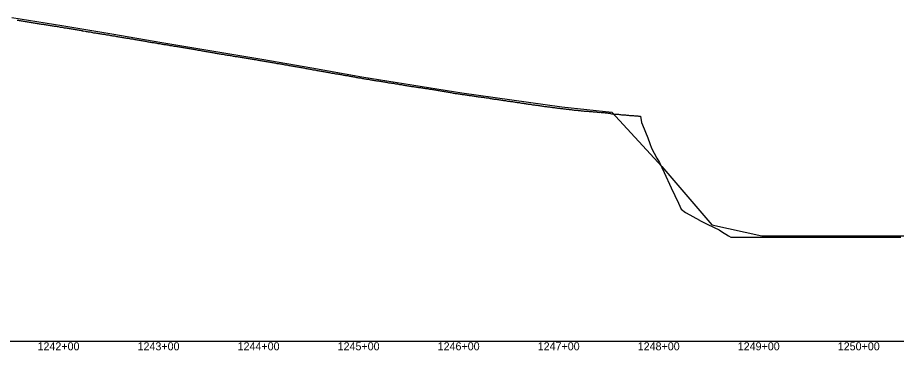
# Model space of a CAD drawing. Extents: x -3793 to 50787, y -1075 to 6138.
# Drawn here: x 11533 to 12412, y -1009 to -677 of the extents above; entities that cross this region are included whole.
import ezdxf

# ---------------------------------------------------------------- set-up
doc = ezdxf.new("R2010")
doc.units = 0
for name, color, linetype in [('RD_DDB_Profile_EX', 7, 'Continuous'), ('RD_DDB_Profile_PR', 7, 'Continuous'), ('RD_DDB_StaTX', 7, 'Continuous'), ('RD_GPK_Profile_Cell', 7, 'Continuous')]:
    doc.layers.add(name, color=color, linetype=linetype)

msp = doc.modelspace()

# ---------------------------------------------------------------- linework, layer by layer
at = {"layer": 'RD_DDB_Profile_EX'}
for points in [[(11532.766979, -678.98741), (11533.770655, -679.093735), (11534.765852, -679.29383), (11535.769737, -679.537725), (11536.765284, -679.63993), (11537.760475, -679.84009), (11538.769144, -679.940305), (11539.764149, -680.188555), (11540.759673, -680.338745), (11541.763232, -680.44254), (11542.758748, -680.7445), (11543.75394, -680.7982), (11544.757823, -680.94642), (11545.752841, -681.04824), (11546.756725, -681.298255), (11547.752219, -681.45), (11548.752221, -681.69835), (11549.756105, -681.8), (11550.751298, -682), (11551.746608, -682.153155), (11552.750219, -682.307825), (11553.745681, -682.501535), (11554.749299, -682.60913), (11555.744755, -682.70894), (11556.7398, -682.952915), (11557.743684, -683.057235), (11558.739124, -683.20708), (11559.739154, -683.358105), (11560.743036, -683.558035), (11561.641476, -683.661995), (11562.636702, -683.813015), (11563.640337, -684.01161), (11564.639413, -684.110495), (11565.634539, -684.358955), (11566.638401, -684.460145), (11567.633743, -684.611125), (11568.637268, -684.86348), (11569.627817, -684.963485), (11570.631464, -685.21093), (11571.635325, -685.264445)], [(11571.635325, -685.264445), (11572.630452, -685.51054), (11573.634313, -685.517405), (11574.629329, -685.86467), (11575.628388, -686.0638), (11576.623515, -686.161175), (11577.627376, -686.217705), (11578.631237, -686.51315), (11579.626364, -686.612755), (11580.625313, -686.76194), (11581.62044, -686.865795), (11582.624301, -687.20938), (11583.619427, -687.262115), (11584.623288, -687.36598), (11585.62688, -687.567785), (11586.617364, -687.715815), (11587.621054, -687.864655), (11588.605712, -688.01229), (11589.609696, -688.215885), (11590.605343, -688.36353), (11591.603885, -688.46479), (11592.607869, -688.76096), (11593.603363, -688.91233), (11594.607255, -689.012185), (11595.602894, -689.20922), (11596.606737, -689.361575), (11597.597083, -689.510765), (11598.601066, -689.95572), (11599.604912, -689.912895), (11600.600459, -690.10929), (11601.604443, -690.30687), (11602.59473, -690.35916), (11603.598633, -690.60979), (11604.594251, -690.66009), (11605.598112, -690.809225), (11606.602022, -691.159085), (11607.206557, -691.160255), (11608.205381, -691.310585), (11609.209278, -691.656945), (11610.208027, -691.70932), (11611.206971, -691.859605), (11612.202332, -692.10989), (11613.201081, -692.16166), (11614.204979, -692.40933), (11615.203925, -692.46036), (11616.19909, -692.611325), (11617.198034, -692.860945), (11618.201932, -693.060065), (11619.200677, -693.112595), (11620.199624, -693.213735), (11621.194988, -693.313885), (11622.193734, -693.61129), (11623.197632, -693.810385), (11624.196581, -693.912985), (11625.200271, -694.11205), (11626.190689, -694.31206), (11627.194458, -694.462625), (11628.193405, -694.61682), (11629.197227, -694.765085), (11630.187515, -694.91584), (11631.186465, -695.113975), (11632.190285, -695.362255), (11633.189101, -695.514965), (11634.192999, -695.664755), (11635.183346, -695.814), (11636.18711, -695.9638), (11637.18606, -696.06892), (11638.189879, -696.36634), (11639.188692, -696.46679), (11640.179123, -696.616805), (11641.182803, -696.86658), (11642.181754, -696.96704), (11643.185653, -697.16521), (11644.184382, -697.21892), (11645.179763, -697.41818), (11646.178716, -697.61706), (11647.182475, -697.818425), (11648.17979, -697.91976), (11649.170142, -698.067315), (11649.546562, -698.116375), (11650.545223, -698.37019), (11651.549223, -698.46827), (11652.547884, -698.717055), (11653.546491, -698.768355), (11654.5504, -699.169005), (11655.549057, -699.169495), (11656.547811, -699.41725), (11657.543412, -699.468405), (11658.542072, -699.667075), (11659.540832, -699.76933), (11660.54458, -700.0182), (11661.543336, -700.2177), (11662.541996, -700.36908), (11663.545896, -700.61793), (11664.544657, -700.71931), (11665.543316, -700.968765), (11666.547213, -701.117595), (11667.537522, -701.27151), (11668.536181, -701.372), (11669.540182, -701.569785), (11670.538842, -701.77023)], [(11670.538842, -701.77023), (11671.537501, -701.87171), (11672.536273, -702.219), (11673.540162, -702.276135), (11674.538641, -702.47241), (11675.537413, -702.571775), (11676.533027, -702.81692), (11677.531802, -703.018345), (11678.530464, -703.07313), (11679.534347, -703.270735), (11680.533125, -703.421145), (11681.531595, -703.52383), (11682.535477, -703.72362), (11683.534255, -703.87178), (11684.532913, -704.121035), (11685.536915, -704.27084), (11686.527315, -704.37086), (11687.525977, -704.57008), (11688.529779, -704.7234), (11689.528437, -704.92146), (11690.527096, -705.12186), (11691.531097, -705.17528), (11692.529755, -705.373295), (11693.528547, -705.5262), (11694.45383, -705.72317), (11695.444036, -705.875625), (11696.44802, -706.07298), (11697.451878, -706.22279), (11698.442414, -706.4216), (11699.446271, -706.5738), (11700.45013, -706.82124), (11701.440661, -706.87361), (11702.44432, -707.12106), (11703.448182, -707.223195), (11704.438708, -707.372045), (11705.442569, -707.569555), (11706.446553, -707.67165), (11707.44212, -707.822165), (11708.440816, -708.026005), (11709.444609, -708.221265), (11710.440177, -708.419585), (11711.438871, -708.52443), (11712.442855, -708.67419), (11713.446725, -708.92397), (11714.437231, -709.07289), (11715.441099, -709.173755), (11716.444789, -709.469245), (11717.435289, -709.668185), (11718.439161, -709.82119), (11719.443035, -710.06994), (11720.43353, -710.171), (11721.437403, -710.270795), (11722.441387, -710.42058), (11723.436947, -710.66895), (11724.43547, -710.77039), (11725.439455, -710.97219), (11726.435017, -711.218565), (11727.43371, -711.31999), (11728.437695, -711.52373), (11729.433253, -711.671055), (11730.432052, -711.82056), (11730.782671, -712.018115), (11731.78642, -712.118865), (11732.776893, -712.31982), (11733.780642, -712.520535), (11734.775776, -712.61894), (11735.779615, -712.77138), (11736.774743, -712.9189), (11737.778432, -713.117805), (11738.768797, -713.220375), (11739.772554, -713.46677), (11740.767757, -713.665315), (11741.771517, -713.76671), (11742.76671, -713.96679), (11743.770473, -714.06656), (11744.769335, -714.167825), (11745.764527, -714.36559), (11746.768293, -714.516835), (11747.763476, -714.666085), (11748.767246, -714.964465), (11749.762418, -715.11575), (11750.761299, -715.26493), (11751.756469, -715.413565), (11752.760244, -715.56398), (11753.755404, -715.616275), (11754.759181, -715.814805), (11755.754233, -716.01286), (11756.753233, -716.113965), (11757.748328, -716.41374), (11758.752163, -716.512925), (11759.755947, -716.663195), (11760.751, -716.811875), (11761.754789, -716.961615), (11762.745137, -717.210665), (11763.748925, -717.4109), (11764.744052, -717.511465), (11765.747768, -717.661185), (11766.742891, -717.90953), (11767.746688, -718.010045), (11768.73701, -718.20929), (11769.733292, -718.357895)], [(11769.733292, -718.357895), (11770.50051, -718.40802), (11771.504453, -718.557775), (11772.503105, -718.758655), (11773.507071, -719.05731), (11774.502688, -719.20665), (11775.501341, -719.456395), (11776.505287, -719.507225), (11777.503936, -719.60807), (11778.499554, -719.80701), (11779.498207, -719.958205), (11780.502211, -720.20657), (11781.497733, -720.356255), (11782.49642, -720.50671), (11783.500389, -720.805515), (11784.499077, -720.90625), (11785.494652, -721.05597), (11786.493286, -721.207075), (11787.497255, -721.40587), (11788.501227, -721.555985), (11789.491518, -721.75663), (11790.495489, -721.856405), (11791.494121, -722.00622), (11792.498092, -722.25538), (11793.488384, -722.35698), (11794.492355, -722.50613), (11795.491042, -722.75724), (11796.494958, -722.90636), (11797.490568, -723.0557), (11798.48922, -723.20616), (11799.493225, -723.405345), (11800.48348, -723.605955), (11801.487434, -723.656015), (11802.486086, -723.90619), (11803.490091, -724.056565), (11804.485664, -724.255835), (11805.484318, -724.45548), (11806.488275, -724.604985), (11807.486924, -724.7093), (11808.361277, -724.955955), (11809.365225, -725.05545), (11810.355506, -725.30492), (11811.359409, -725.45472), (11812.363387, -725.753765), (11813.353636, -725.854535), (11814.357613, -726.054815), (11815.361565, -726.154595), (11816.351795, -726.35438), (11817.355748, -726.45439), (11818.359726, -726.70354), (11819.349968, -726.853555), (11820.353922, -727.152575), (11821.3596, -727.25318), (11822.349847, -727.45357), (11823.353702, -727.603185), (11824.357548, -727.802815), (11825.356465, -727.95321), (11826.351649, -728.152485), (11827.355511, -728.302455), (11828.354443, -728.602675), (11829.349624, -728.702145), (11830.353486, -728.901965), (11831.352419, -729.151895), (11832.347595, -729.2518), (11833.351459, -729.401825), (11834.350369, -729.651865), (11835.345547, -729.801455), (11836.349414, -730.10104), (11837.348342, -730.20144), (11838.343516, -730.400765), (11839.347384, -730.5007), (11840.346304, -730.65114), (11840.894582, -730.750955), (11841.893258, -730.95113), (11842.891925, -731.10151), (11843.890592, -731.251785), (11844.886127, -731.551385), (11845.884794, -731.65166), (11846.883462, -731.901615), (11847.882149, -732.001845), (11848.880818, -732.152285), (11849.879488, -732.35323), (11850.883461, -732.60308), (11851.882154, -732.6534), (11852.880824, -732.80319), (11853.879494, -733.004045), (11854.878197, -733.15468), (11855.882108, -733.354515), (11856.880774, -733.455185), (11857.879477, -733.75451), (11858.878145, -733.90592), (11859.876814, -734.005895), (11860.88077, -734.354205), (11861.879479, -734.45486), (11862.878147, -734.55642), (11863.876815, -734.805865), (11864.875534, -735.056635), (11865.879402, -735.10648), (11866.878067, -735.35826), (11867.876785, -735.45814), (11868.883541, -735.76011)], [(11868.883541, -735.76011), (11869.882559, -735.812215), (11870.886387, -736.20816), (11871.885405, -736.309075), (11872.884422, -736.361215), (11873.88344, -736.65981), (11874.882519, -736.711445), (11875.886286, -736.86438), (11876.885304, -737.21167), (11877.875635, -737.41234), (11878.967898, -737.510865), (11879.966878, -737.664745), (11880.965859, -737.814505), (11881.969635, -737.965005), (11882.968685, -738.066215), (11883.967533, -738.215955), (11884.966509, -738.415655), (11885.970281, -738.565445), (11886.969256, -738.723065), (11887.96831, -738.96881), (11888.967286, -739.06934), (11889.966263, -739.268145), (11890.970027, -739.466215), (11891.969087, -739.665765), (11892.968063, -739.76798), (11893.958436, -739.868005), (11894.957417, -740.118465), (11895.961262, -740.21733), (11896.960243, -740.37151), (11897.959224, -740.52108), (11898.958204, -740.67159), (11899.96205, -740.82231), (11900.96103, -741.019865), (11901.960011, -741.16931), (11902.958992, -741.270785), (11903.957786, -741.61699), (11904.961633, -741.667865), (11905.96061, -741.86718), (11906.959587, -741.92194), (11907.958563, -742.07352), (11908.962411, -742.223285), (11909.961387, -742.471505), (11910.960364, -742.574255), (11911.95934, -742.778275), (11912.958434, -742.878805), (11913.962164, -743.07618), (11914.961141, -743.323045), (11915.960117, -743.37596), (11916.959216, -743.526425), (11917.958195, -743.67691), (11919.049142, -743.92229), (11920.04328, -744.077355), (11921.050695, -744.228245), (11922.044983, -744.42935), (11923.043921, -744.57981), (11924.046263, -744.776645), (11925.045195, -744.925445), (11926.047948, -745.08), (11927.04688, -745.22872), (11928.04105, -745.37967), (11929.048394, -745.52863), (11930.042751, -745.681345), (11931.050079, -745.783985), (11932.044264, -745.892755), (11933.043198, -746.039325), (11934.045965, -746.284705), (11935.044899, -746.387155), (11936.047458, -746.44281), (11937.046391, -746.63894), (11938.048937, -746.794785), (11939.048091, -746.99069), (11940.042318, -747.18936), (11941.049563, -747.240105), (11942.043795, -747.34586), (11943.051263, -747.50157), (11944.045505, -747.647695), (11945.043998, -747.895575), (11946.046508, -748.18389), (11947.045697, -748.192045), (11948.048201, -748.30406), (11949.025804, -748.493595), (11950.019642, -748.64168), (11951.026755, -748.80358), (11952.020605, -749.045985), (11952.773872, -749.190385), (11953.772748, -749.38779), (11954.774532, -749.49172), (11955.773703, -749.73901), (11956.772576, -749.81046), (11957.771754, -750.04261), (11958.778756, -750.18395), (11959.772914, -750.4471), (11960.771557, -750.55054), (11961.770428, -750.69772), (11962.769621, -750.801225), (11963.776594, -750.995415), (11964.770765, -751.142865), (11965.76997, -751.47986), (11966.768844, -751.53006), (11967.775549, -751.687165), (11968.774417, -751.89081)], [(11968.774417, -751.89081), (11969.768949, -752.04142), (11970.767822, -752.23474), (11971.766695, -752.334965), (11972.773972, -752.531825), (11973.772843, -752.682025), (11974.771455, -752.800075), (11975.76566, -752.893555), (11976.764532, -753.13652), (11977.771796, -753.240605), (11978.770666, -753.39085), (11979.769912, -753.441065), (11980.763484, -753.64163), (11981.770737, -753.795885), (11982.479238, -753.89178), (11983.478246, -754.13056), (11984.477625, -754.2384), (11985.476636, -754.33862), (11986.480467, -754.488515), (11987.478796, -754.684845), (11988.477803, -754.83115), (11989.477188, -754.89305), (11990.480643, -755.089055), (11991.480028, -755.23925), (11992.479037, -755.431575), (11993.478046, -755.577785), (11994.481182, -755.655395), (11995.480187, -755.839785), (11996.479578, -755.901975), (11997.478586, -756.048245), (11998.482418, -756.198115), (11999.481425, -756.34435), (12000.399474, -756.528365), (12001.475474, -756.732175), (12002.474482, -756.7647), (12003.473881, -756.86501), (12004.47289, -757.10311), (12005.476329, -757.24485), (12006.475731, -757.528675), (12007.474016, -757.587055), (12008.473421, -757.699635), (12009.394407, -757.88301), (12009.802806, -757.895585), (12010.806297, -758.078955), (12011.805564, -758.19571), (12012.809054, -758.33733), (12013.808322, -758.45417), (12014.803175, -758.6831), (12015.802443, -758.833255), (12016.805932, -758.89149), (12017.804779, -759.04588), (12018.80405, -759.241905), (12019.807536, -759.341825), (12020.79817, -759.533445), (12021.801657, -759.68755), (12022.800504, -759.883555), (12023.804414, -759.89184), (12024.803261, -760.133645), (12025.807171, -760.279365), (12026.798107, -760.34198), (12027.801293, -760.53348), (12028.800139, -760.68366), (12029.750652, -760.82537), (12030.753517, -761.116875), (12031.744887, -761.12953), (12032.748461, -761.30474), (12033.747514, -761.4923), (12034.835111, -761.496415), (12035.749429, -761.63392), (12036.837963, -761.89231), (12037.744376, -762.02962), (12038.832001, -762.154875), (12039.746291, -762.246655), (12040.834853, -762.446555), (12041.748916, -762.62977), (12042.740294, -762.729765), (12043.743865, -762.9882), (12044.827362, -763.101165), (12045.905137, -763.151235), (12046.908561, -763.35114), (12047.907972, -763.58425), (12048.898188, -763.638535), (12049.902025, -763.83417), (12050.901438, -764.02574), (12051.90486, -764.05139), (12052.903519, -764.193), (12053.902514, -764.351865), (12054.906353, -764.493115), (12055.905348, -764.652), (12056.901162, -764.75164), (12057.899403, -764.943235), (12058.898819, -765.093425), (12059.902237, -765.280345), (12060.901654, -765.38483), (12061.900652, -765.44376), (12062.903723, -765.55236), (12063.902717, -765.78947), (12064.898542, -765.843555), (12065.89754, -765.99815), (12066.896964, -766.143965), (12067.90003, -766.239455)], [(12067.90003, -766.239455), (12068.899026, -766.35287), (12069.902864, -766.493955), (12070.90186, -766.776505), (12071.812201, -766.86775), (12072.895914, -766.939665), (12073.895339, -767.016395), (12074.898749, -767.1707), (12075.898175, -767.25769), (12076.89639, -767.39458), (12077.900229, -767.49892), (12078.899223, -767.621505), (12079.813531, -767.803515), (12080.501755, -767.85343), (12081.497519, -767.953105), (12082.500746, -768.09854), (12083.491703, -768.13974), (12084.495681, -768.239645), (12085.49144, -768.393775), (12086.494675, -768.49365), (12087.490892, -768.64335), (12088.494413, -768.706255), (12089.490622, -768.938675), (12090.494147, -768.997185), (12091.497397, -769.00132), (12092.493152, -769.146745), (12093.497131, -769.246625), (12094.492882, -769.342115), (12095.49686, -769.45041), (12096.487066, -769.55462), (12097.491044, -769.65029), (12098.48679, -769.69996), (12099.490768, -769.90398), (12100.48651, -769.9495), (12101.489787, -770.007575), (12102.493332, -770.061565), (12103.489507, -770.157035), (12104.535492, -770.30695), (12105.530545, -770.36064), (12106.53432, -770.364625), (12107.530074, -770.46023), (12108.533849, -770.656165), (12109.524368, -770.71025), (12110.528143, -770.672235), (12111.52389, -770.825795), (12112.526969, -770.971705), (12113.530745, -771.11368), (12114.526877, -771.22116), (12115.530653, -771.17899), (12116.525701, -771.270625), (12117.529477, -771.38231), (12118.525206, -771.439595), (12119.528983, -771.53561), (12120.52403, -771.68117), (12121.527807, -771.734945), (12122.518992, -771.838965), (12123.522093, -772.000415), (12124.525871, -772.16188), (12125.444831, -772.11482), (12125.979652, -772.394795), (12126.975601, -772.544175), (12127.975767, -772.55384), (12128.97657, -772.64859), (12129.972501, -772.887025), (12130.973294, -772.98564), (12131.973485, -772.998245), (12132.974282, -773.139715), (12133.970186, -773.189035), (12134.945197, -773.23725), (12136.012093, -773.388785), (12136.94232, -773.62164), (12137.943191, -773.62655), (12138.94442, -773.62801), (12139.940135, -773.67407), (12140.941535, -773.78156), (12141.942761, -773.923785), (12143.001574, -774.024975), (12143.947726, -774.11895), (12144.948959, -774.272895), (12145.949891, -774.321145), (12146.945611, -774.275655), (12147.947291, -774.41585), (12148.948237, -774.511595), (12149.943956, -774.6209), (12150.945604, -774.568985), (12152.171975, -774.64925), (12153.112138, -774.742415), (12154.051732, -774.931015), (12154.997285, -774.88275), (12155.987275, -775.0903), (12156.989604, -781.31992), (12157.998796, -783.76733), (12163.367701, -796.787825), (12165.166881, -802.33118), (12166.744192, -807.13371), (12172.334966, -817.063855), (12174.762786, -821.374465), (12179.50305, -831.422005), (12186.671135, -846.61471), (12193.83922, -861.806505), (12196.720192, -867.847595)], [(12196.720192, -867.847595), (12201.007305, -871.275285), (12201.413718, -871.60016), (12208.175389, -875.39921), (12214.749619, -879.07556), (12215.343474, -879.3655), (12222.511559, -882.86449), (12229.679644, -886.362735), (12234.495576, -888.712555), (12236.847728, -890.194775), (12244.015813, -894.70963), (12246.144885, -896.05), (12249.058197, -896.05), (12251.183898, -896.05), (12253.296147, -896.05), (12258.351983, -896.05), (12263.370128, -896.05), (12265.520067, -896.05), (12266.727949, -896.05), (12271.460802, -896.05), (12272.688152, -896.05), (12279.856237, -896.05), (12287.024322, -896.05), (12294.192406, -896.05), (12301.360491, -896.05), (12308.528576, -896.05), (12315.696661, -896.05), (12322.864745, -896.05), (12330.03283, -896.05), (12337.200915, -896.05), (12344.41227, -896.05), (12351.537084, -896.05), (12355.360186, -896.05), (12358.705169, -896.05), (12365.873254, -896.05), (12373.041338, -896.05), (12380.209423, -896.05), (12387.377508, -896.05), (12394.545593, -896.05), (12399.882494, -896.05), (12401.713677, -896.05), (12408.271783, -896.05), (12408.881762, -896.05), (12416.049847, -896.05)]]:
    msp.add_lwpolyline(points, dxfattribs=at)
at = {"layer": 'RD_DDB_Profile_PR'}
msp.add_lwpolyline([(11527.33, -676.527), (11577.33, -684.601), (11627.33, -692.8835), (11677.33, -701.3775), (11727.33, -709.7095), (11777.33, -717.9905), (11827.33, -726.6985), (11877.33, -735.702), (11927.33, -743.6715), (11977.33, -751.595), (12027.33, -758.8435), (12077.33, -765.8395), (12127.33, -770.9475), (12177.33, -825.216), (12227.33, -883.616), (12277.33, -894.45), (12327.33, -894.45), (12377.33, -894.45), (12427.33, -894.45)], dxfattribs=at)
at = {"layer": 'RD_GPK_Profile_Cell'}
msp.add_line((1000, -1000), (46610.921919, -1000), dxfattribs=at)

# ---------------------------------------------------------------- texts
at = {"layer": 'RD_DDB_StaTX'}
for s, p in [('1242+00', (11553.125471, -1009)), ('1242+00', (11553.125471, -1009)), ('1243+00', (11653.125471, -1009)), ('1243+00', (11653.125471, -1009)), ('1244+00', (11753.125471, -1009)), ('1244+00', (11753.125471, -1009)), ('1245+00', (11853.125471, -1009)), ('1245+00', (11853.125471, -1009)), ('1246+00', (11953.125471, -1009)), ('1246+00', (11953.125471, -1009)), ('1247+00', (12053.125471, -1009)), ('1247+00', (12053.125471, -1009)), ('1248+00', (12153.125471, -1009)), ('1248+00', (12153.125471, -1009)), ('1249+00', (12253.125471, -1009)), ('1249+00', (12253.125471, -1009)), ('1250+00', (12353.125471, -1009)), ('1250+00', (12353.125471, -1009))]:
    msp.add_text(s, height=8, dxfattribs=at).set_placement(p)

doc.saveas('drawing.dxf')
